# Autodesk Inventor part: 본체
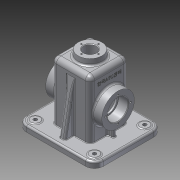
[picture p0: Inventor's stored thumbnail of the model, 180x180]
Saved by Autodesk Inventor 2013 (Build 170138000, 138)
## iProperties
Created: 2016-01
Part Number: 본체
Material: 알루미늄 6061
Document SubType Name: Modeling
Designer: User
Density: 2.71 g/cm^3
Mass: 858.396 g
Surface Area: 910.857 cm^2
Volume: 316.751 cm^3
Author: User
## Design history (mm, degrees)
sketch "스케치1"
  geometry: L1 (-65, -57.5)-(65, -57.5); L2 (65, -57.5)-(65, 57.5); L3 (65, 57.5)-(-65, 57.5); L4 (-65, 57.5)-(-65, -57.5); L5 (-65, -57.5)-(65, 57.5); L6 (65, -57.5)-(-65, 57.5); 1 further point
  constraints: 12 end point, 2 midpoint, 2 parallel, 1 horizontal, 1 perpendicular
  dimensions: "d0" = 130 distance of L2.end L3.end; "d2" = 115 distance of L1.end L2.end
extrude "돌출1" new body sketch "스케치1" distance "d3" = 10; taper "d4" = 0 deg
sketch "스케치2"
  geometry: L1 (-60, -52.5)-(60, -52.5); L2 (60, -52.5)-(60, 52.5); L3 (60, 52.5)-(-60, 52.5); L4 (-60, 52.5)-(-60, -52.5); L5 (-60, -52.5)-(60, 52.5); L6 (60, -52.5)-(-60, 52.5); 1 further point
  constraints: 12 end point, 2 midpoint, 2 parallel, 1 horizontal, 1 perpendicular
  dimensions: "d5" = 120 distance of L2.end L3.end; "d7" = 105 distance of L1.end L2.end
extrude "돌출2" join sketch "스케치2" distance "d8" = 2; taper "d9" = 0 deg
sketch "스케치3"
  geometry: L1 (-32.5, -32.5)-(32.5, -32.5); L2 (32.5, -32.5)-(32.5, 32.5); L3 (32.5, 32.5)-(-32.5, 32.5); L4 (-32.5, 32.5)-(-32.5, -32.5); L5 (-32.5, -32.5)-(32.5, 32.5); L6 (32.5, -32.5)-(-32.5, 32.5); 1 further point
  constraints: 12 end point, 2 midpoint, 2 parallel, 1 horizontal, 1 perpendicular
  dimensions: "d10" = 65 distance of L2.end L3.end; "d12" = 65 distance of L1.end L2.end
extrude "돌출3" join sketch "스케치3" distance "d13" = 98; taper "d14" = 0 deg
sketch "스케치4"
  geometry: C1 r 20 at (0, 0); 1 further point
  constraints: 1 centre point, 1 coincident
  dimensions: "d15" = 40 diameter of C1
extrude "돌출4" join sketch "스케치4" distance "d17" = 10; taper "d18" = 0 deg
feature "면 기울기1" dims angle "d19" = 5 deg
sketch "스케치5"
  geometry: C1 r 27.5 at (-43, 32.5); 1 further point
  constraints: 1 centre point, 1 horizontal alignment
  dimensions: "d20" = 55 diameter of C1; "d22" = 53 distance of point (10, 32.5) C1.centre
extrude "돌출5" join sketch "스케치5" distance "d23" = 15; taper "d24" = 0 deg
sketch "스케치7"
  geometry: L1 (32.5, -32.5)-(-32.5, -32.5) reference; L2 (0, 0)-(0, 25.72); L3 (0, 0)-(16.636, 0); C1 r 7.5 at (-50, 42.5); C2 r 7.5 at (50, 42.5); C3 r 7.5 at (-50, -42.5); C4 r 7.5 at (50, -42.5); 1 further point
  constraints: 4 centre point, 4 end point, 3 symmetric about line, 2 perpendicular, 3 other
  dimensions: "d30" = 15 diameter of C1; "d32" = 100 diameter of C1.centre L2; "d33" = 85 diameter of C1.centre L3
extrude "돌출7" join sketch "스케치7" distance "d34" = 1; taper "d35" = 0 deg
hole "구멍1" diameter "d38" = 6; stored, may be unused: countersink angle "d42" = 90 deg, drill point angle "d44" = 118 deg; dims "d36" = 10, "d37" = 10, "d39" = 6, "d40" = 4, "d41" = 2, "d43" = 8
hole "구멍2" diameter "d47" = 6; stored, may be unused: countersink angle "d51" = 90 deg, drill point angle "d53" = 118 deg; dims "d45" = 10, "d46" = 10, "d48" = 6, "d49" = 4, "d50" = 2, "d52" = 8
hole "구멍3" diameter "d56" = 6; stored, may be unused: countersink angle "d60" = 90 deg, drill point angle "d62" = 118 deg; dims "d54" = 10, "d55" = 10, "d57" = 6, "d58" = 4, "d59" = 2, "d61" = 8
hole "구멍4" diameter "d65" = 6; stored, may be unused: countersink angle "d69" = 90 deg, drill point angle "d71" = 118 deg; dims "d63" = 10, "d64" = 10, "d66" = 6, "d67" = 4, "d68" = 2, "d70" = 8
sketch "스케치8"
  geometry: L1 (-27.5, -27.5)-(27.5, -27.5); L2 (27.5, -27.5)-(27.5, 27.5); L3 (27.5, 27.5)-(-27.5, 27.5); L4 (-27.5, 27.5)-(-27.5, -27.5); L5 (-27.5, -27.5)-(27.5, 27.5); L6 (27.5, -27.5)-(-27.5, 27.5); 1 further point
  constraints: 12 end point, 2 midpoint, 2 parallel, 1 horizontal, 1 perpendicular
  dimensions: "d72" = 55 distance of L2.end L3.end; "d74" = 55 distance of L1.end L2.end
extrude "돌출8" cut sketch "스케치8" distance "d75" = 105; taper "d76" = 0 deg
sketch "스케치9"
  geometry: C1 r 20 at (0, 0) reference; C2 r 10.5 at (0, 0)
  constraints: 1 centre point, 1 coincident
  dimensions: "d77" = 21 diameter of C2
extrude "돌출9" cut sketch "스케치9" distance "d79" = 105; taper "d80" = 0 deg
sketch "스케치11"
  geometry: C1 r 27.5 at (0, 0) reference; C2 r 17.5 at (0, 0); 1 further point
  constraints: 1 centre point, 1 coincident
  dimensions: "d84" = 35 diameter of C2
extrude "돌출11" cut sketch "스케치11" distance "d86" = 17; taper "d87" = 0 deg
sketch "스케치12"
  geometry: C1 r 17.5 at (0, 0) reference; C2 r 15 at (0, 0); 1 further point
  constraints: 1 centre point, 1 coincident
  dimensions: "d88" = 30 diameter of C2
extrude "돌출12" cut sketch "스케치12" distance "d90" = 17; taper "d91" = 0 deg
sketch "스케치13" dims "d92" = 29
  geometry: L1 (0, 0)-(0, 16.83); C1 r 20 at (0, 0) reference; 1 further point
  constraints: 2 end point, 1 coincident, 1 point on line, 1 vertical, 1 vertical alignment, 2 other
hole "구멍5" sketch "스케치13" at (0, 14.5) diameter "d94" = 2.459; stored, may be unused: countersink angle "d98" = 90 deg, drill point angle "d100" = 118 deg; dims "d95" = 7, "d96" = 4, "d97" = 2, "d99" = 9
sketch "스케치14" dims "d104" = 42
  geometry: L1 (0, 0)-(-38.866, 0); C1 r 27.5 at (0, 0) reference; 2 further points
  constraints: 2 end point, 1 coincident, 1 horizontal, 1 horizontal alignment, 1 point on line, 2 other
hole "구멍6" sketch "스케치14" at (-21, 0) diameter "d106" = 3.242; stored, may be unused: countersink angle "d110" = 90 deg, drill point angle "d112" = 118 deg; dims "d107" = 8, "d108" = 4, "d109" = 2, "d111" = 10
fillet "모깎기1" dims "d116" = 15
fillet "모깎기2" dims "d117" = 8
fillet "모깎기3" dims "d118" = 10
sketch "스케치15"
  geometry: L1 (-10, 52.5)-(-10, 12.5) reference; A1 r 27.5 centre (55, 32.5) between (82.5, 32.5) and (82.5, 32.5) reference; 2 further points
  constraints: 1 horizontal alignment, 1 other
  dimensions: "d119" = 26 distance from line of L1 point (16, 32.5)
feature "엠보싱1" sketch "스케치15" dims "d10" = 65, "d12" = 65, "d120" = 0.5, "d121" = 0
fillet "모깎기4" dims "d122" = 3
fillet "모깎기5" dims "d123" = 0.3
chamfer "모따기1" distance "d125" = 1; stored, may be unused: second distance "d126" = 2, angle "d127" = 45 deg
fillet "모깎기7" dims "d128" = 3
sketch "스케치16"
  geometry: L1 (28.085, -3)-(39.5, -3); L2 (39.5, 3)-(28.085, 3); L3 (28.085, 3)-(28.085, -3); L4 (28.085, -3)-(39.5, 3); L5 (39.5, -3)-(28.085, 3); L6 (27.5, -27.5)-(27.5, 27.5) reference; A1 r 3 centre (39.5, 0) between (39.5, -3) and (39.5, 3); 2 further points
  constraints: 10 end point, 2 midpoint, 2 point on circle, 2 tangent, 1 centre point, 1 horizontal, 1 horizontal alignment, 1 parallel, 1 perpendicular
  dimensions: "d129" = 15 dimension on A1 L6; "d130" = 6 distance between parallel lines of L1 L2
extrude "돌출13" join sketch "스케치16" distance "d131" = 17; taper "d132" = 0 deg
sketch "스케치17"
  geometry: L1 (47.5, 10)-(31.384, 101.398); L2 (31.384, 101.398)-(31.384, 10); L3 (31.384, 10)-(47.5, 10); L4 (52.236, 10)-(32.764, 10) reference; L5 (57.5, 10)-(57.5, 0) reference; 2 further points
  constraints: 6 end point, 1 midpoint, 1 perpendicular, 1 point on line, 1 vertical
  dimensions: "d134" = 10 distance from line of L5 L1.start; "d135" = 10 deg angle of L1 L5
extrude "돌출14" join sketch "스케치17" stored distance "d136" = 10; taper "d137" = 0 deg
fillet "모깎기9" dims "d138" = 3
fillet "모깎기10" dims "d139" = 3
fillet "모깎기11" dims "d140" = 3
fillet "모깎기12" dims "d141" = 3
fillet "모깎기13" dims "d142" = 1
fillet "모깎기14" dims "d143" = 3
node "솔리드1"
mirror "대칭1"
mirror "대칭4"
pattern_circular "원형 패턴1" dims angle "d102" = 360 deg
pattern_circular "원형 패턴2" dims angle "d114" = 360 deg
mirror "대칭5"
mirror "대칭6"
mirror "대칭7"
